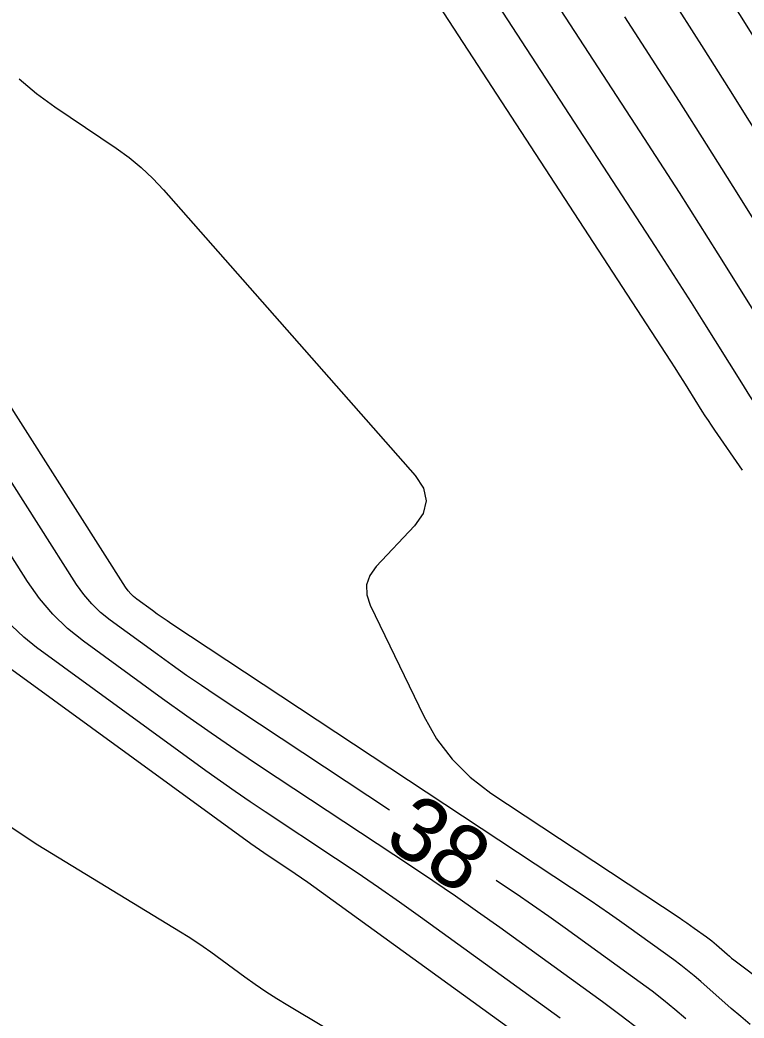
# Model space of a CAD drawing. Extents: x 2384780 to 2405861, y 547869 to 573706.
# Drawn here: x 2390246.48 to 2390269.11, y 552417.78 to 552448.97 of the extents above; entities that cross this region are included whole.
import ezdxf

# ---------------------------------------------------------------- set-up
doc = ezdxf.new("R2010")
doc.units = 0
doc.layers.add('Old_Level_60', color=7, linetype='Continuous')
doc.layers.add('Old_Level_61', color=7, linetype='Continuous')

msp = doc.modelspace()

# ---------------------------------------------------------------- linework, layer by layer
at = {"layer": 'Old_Level_60'}
for points in [[(2390253.77725, 552473.1685), (2390260.52775, 552462.32375), (2390261.27025, 552461.1375), (2390262.01875, 552459.95525), (2390262.77325, 552458.77675), (2390263.53375, 552457.602), (2390266.028, 552453.771), (2390266.5605, 552452.949), (2390267.0895, 552452.1245), (2390267.61475, 552451.29775), (2390268.13625, 552450.4685), (2390272.793, 552443.0285)], [(2390250.31025, 552466.684), (2390252.179, 552463.68175), (2390252.581, 552463.0395), (2390252.98625, 552462.39925), (2390253.395, 552461.761), (2390253.80675, 552461.125), (2390266.32625, 552441.895), (2390266.7035, 552441.31275), (2390267.078, 552440.729), (2390267.45, 552440.14325), (2390267.8195, 552439.556), (2390269.02175, 552437.635), (2390269.28175, 552437.225), (2390269.54675, 552436.818), (2390269.8165, 552436.4145), (2390270.09075, 552436.01375), (2390270.38925, 552435.58375)], [(2390249.31475, 552465.27075), (2390249.3575, 552465.2015), (2390249.4005, 552465.132), (2390249.4435, 552465.06275), (2390250.33925, 552463.62375), (2390250.532, 552463.31575), (2390250.72625, 552463.009), (2390250.922, 552462.703), (2390251.1195, 552462.398), (2390266.803, 552438.3085), (2390266.941, 552438.0955), (2390267.078, 552437.88175), (2390267.21425, 552437.6675), (2390267.34925, 552437.45275), (2390267.78925, 552436.74975), (2390267.88425, 552436.59975), (2390267.98125, 552436.451), (2390268.08, 552436.30325), (2390268.18025, 552436.1565), (2390269.05025, 552434.903)], [(2390256.494, 552459.85175), (2390265.84975, 552445.48175), (2390266.466, 552444.53025), (2390267.07825, 552443.576), (2390267.686, 552442.61925), (2390268.28975, 552441.6595), (2390270.65625, 552437.87825)], [(2390265.373, 552449.06825), (2390266.2285, 552447.7475), (2390267.07825, 552446.42325), (2390267.922, 552445.095), (2390268.75975, 552443.763), (2390272.3, 552438.10675)], [(2390249.7805, 552431.23925), (2390244.36475, 552439.74025)], [(2390258.02575, 552424.27775), (2390252.61225, 552427.85925), (2390252.14775, 552428.17025), (2390251.68675, 552428.4865), (2390251.22925, 552428.808), (2390250.7755, 552429.1345), (2390249.29875, 552430.20975), (2390248.9955, 552430.4525), (2390248.719, 552430.72025), (2390248.46875, 552431.013), (2390248.24525, 552431.33075), (2390244.704, 552436.889)], [(2390246.71, 552431.422), (2390244.79225, 552434.43225), (2390244.661, 552434.63875)], [(2390256.34075, 552422.76525), (2390254.1425, 552424.2195), (2390253.67325, 552424.53375), (2390253.2075, 552424.85325), (2390252.7455, 552425.178), (2390252.287, 552425.50775), (2390246.99725, 552429.35925), (2390246.59525, 552429.6815), (2390246.22825, 552430.03675), (2390245.8965, 552430.425), (2390245.59975, 552430.8465), (2390245.1885, 552431.49225)], [(2390265.83425, 552417.40225), (2390265.26225, 552417.848), (2390264.67925, 552418.28), (2390261.47, 552420.60075), (2390260.78, 552421.0945), (2390260.08475, 552421.58075), (2390259.3845, 552422.06), (2390258.67925, 552422.532), (2390253.996, 552425.63), (2390253.221, 552426.149), (2390252.45175, 552426.67675), (2390251.68875, 552427.213), (2390250.9315, 552427.75775), (2390248.46775, 552429.55175), (2390247.962, 552429.957), (2390247.50025, 552430.40375), (2390247.083, 552430.892), (2390246.71, 552431.422)], [(2390269.2995, 552417.577), (2390269.0015, 552417.8245), (2390268.70825, 552418.0775), (2390267.75775, 552418.914), (2390267.552, 552419.0905), (2390267.34225, 552419.26225), (2390267.1285, 552419.42875), (2390266.9105, 552419.59025), (2390265.51075, 552420.60275), (2390265.2095, 552420.818), (2390264.90625, 552421.03025), (2390264.60075, 552421.23925), (2390264.29325, 552421.445), (2390251.2285, 552430.08825), (2390251.07425, 552430.1915), (2390250.9215, 552430.29625), (2390250.76975, 552430.403), (2390250.6195, 552430.51125), (2390250.12975, 552430.86775), (2390250.02925, 552430.94825), (2390249.9375, 552431.037), (2390249.85475, 552431.134), (2390249.7805, 552431.23925)], [(2390261.5835, 552414.13425), (2390254.849, 552418.16475), (2390254.505, 552418.37575), (2390254.166, 552418.59475), (2390253.83225, 552418.82125), (2390253.5035, 552419.05525), (2390252.43775, 552419.8325), (2390252.20775, 552419.99675), (2390251.9745, 552420.156), (2390251.738, 552420.31025), (2390251.49825, 552420.46), (2390247.03975, 552423.17775), (2390246.11175, 552423.79275)], [(2390263.36, 552417.77225), (2390258.9945, 552420.92925), (2390258.33825, 552421.3985), (2390257.67725, 552421.861), (2390257.01125, 552422.3165), (2390256.34075, 552422.76525)], [(2390267.28775, 552417.7485), (2390266.942, 552418.0455), (2390266.5895, 552418.334), (2390266.23, 552418.61375), (2390265.864, 552418.88525), (2390263.511, 552420.58675), (2390263.005, 552420.94875), (2390262.49525, 552421.30525), (2390261.982, 552421.6565), (2390261.46475, 552422.0025), (2390261.36175, 552422.07075)]]:
    msp.add_lwpolyline(points, dxfattribs=at)
at = {"layer": 'Old_Level_61'}
for points in [[(2390267.08275, 552449.273), (2390267.853, 552448.0605), (2390268.61775, 552446.84475), (2390273.9435, 552438.33525)], [(2390246.45475, 552447.1295), (2390246.9945, 552446.678), (2390247.56625, 552446.26225), (2390249.485, 552444.9615), (2390249.88575, 552444.671), (2390250.266, 552444.357), (2390250.6255, 552444.0195), (2390250.96425, 552443.65875), (2390258.828, 552434.736), (2390259.09075, 552434.338), (2390259.174, 552433.9425), (2390259.07825, 552433.55), (2390258.80325, 552433.16025), (2390257.61225, 552431.892), (2390257.40925, 552431.61225), (2390257.3105, 552431.3165), (2390257.316, 552431.0045), (2390257.426, 552430.67675), (2390259.09975, 552427.207), (2390259.4995, 552426.4995), (2390259.982, 552425.864), (2390260.54675, 552425.3005), (2390261.194, 552424.809), (2390267.07825, 552420.91625), (2390267.198, 552420.836), (2390267.317, 552420.7545), (2390267.435, 552420.672), (2390267.55225, 552420.588), (2390267.934, 552420.312), (2390268.015, 552420.252), (2390268.0945, 552420.19), (2390268.1725, 552420.12625), (2390268.249, 552420.0605), (2390268.5765, 552419.7725), (2390268.64725, 552419.71125), (2390268.71925, 552419.65175), (2390268.79225, 552419.5935), (2390268.86625, 552419.5365), (2390279.839, 552411.2725)], [(2390253.6925, 552423.2215), (2390245.02925, 552429.529), (2390244.96925, 552429.57725), (2390244.91425, 552429.6305), (2390244.8645, 552429.6885), (2390244.82025, 552429.75175), (2390244.68375, 552429.96575), (2390244.6545, 552430.01175), (2390244.6255, 552430.0575), (2390244.5965, 552430.1035), (2390244.5675, 552430.14975), (2390241.994, 552434.2505)], [(2390262.04075, 552417.2645), (2390255.663, 552421.8765), (2390255.47, 552422.01425), (2390255.276, 552422.15025), (2390255.08025, 552422.284), (2390254.88325, 552422.41575), (2390254.2375, 552422.843), (2390254.0995, 552422.9355), (2390253.96275, 552423.02925), (2390253.827, 552423.12475), (2390253.6925, 552423.2215)]]:
    msp.add_lwpolyline(points, dxfattribs=at)

# ---------------------------------------------------------------- texts
at = {"layer": 'Old_Level_60'}
msp.add_text('38', height=2, rotation=326.512389, dxfattribs=at).set_placement((2390257.796, 552423.23075))

doc.saveas('drawing.dxf')
